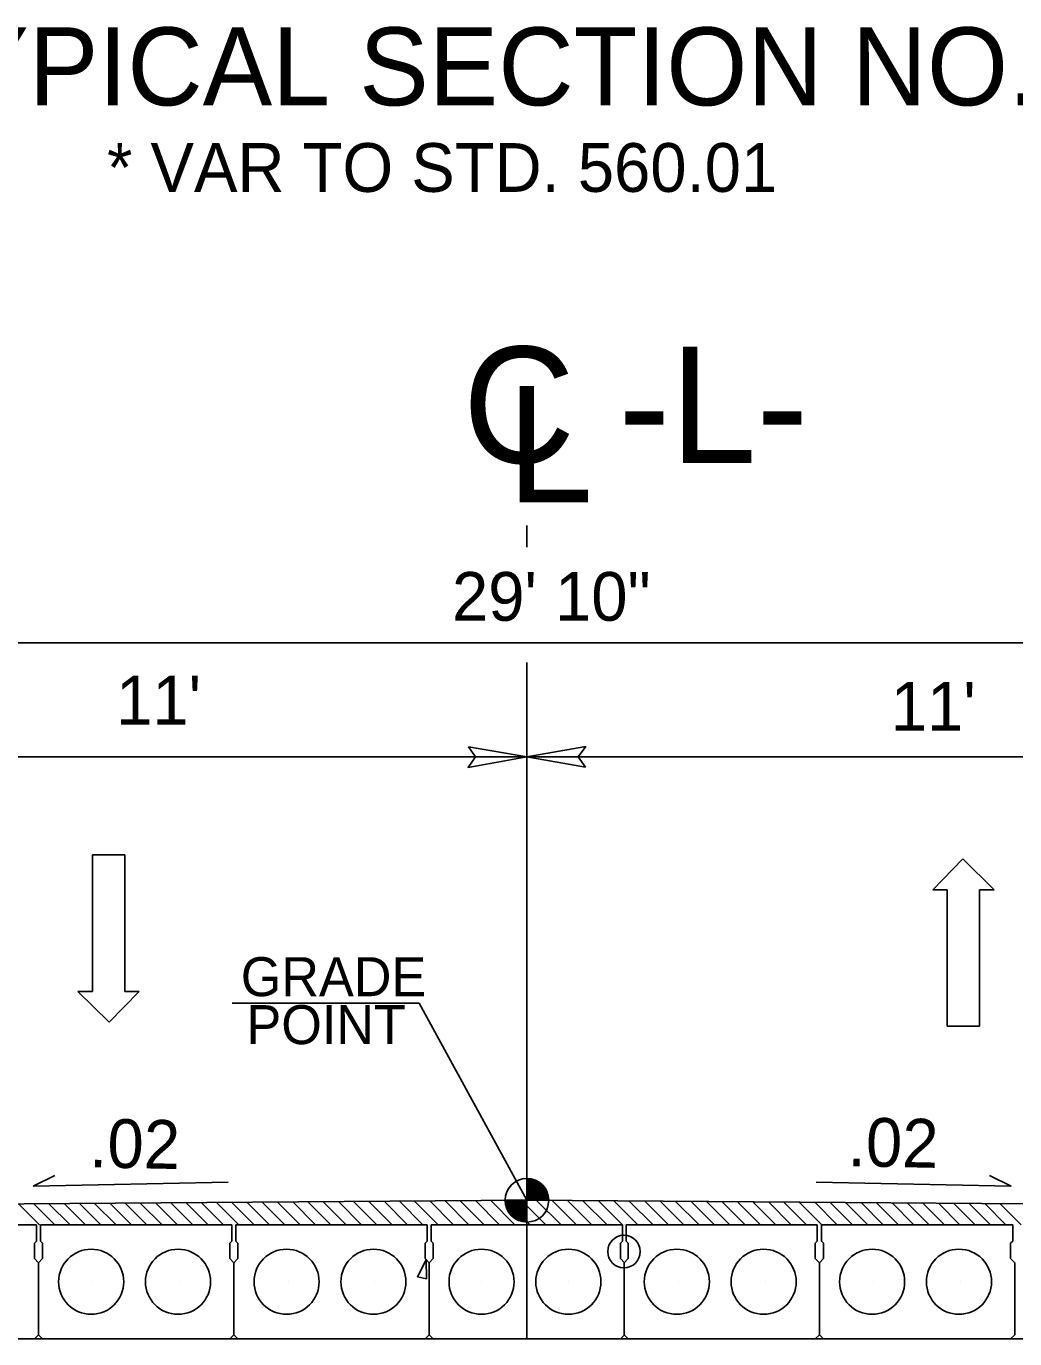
# Model space of a CAD drawing. Extents: x 575722 to 576066, y -53107 to -52774.
# Drawn here: x 575897.08 to 575912.29, y -52878.83 to -52858.63 of the extents above; entities that cross this region are included whole.
import ezdxf

# ---------------------------------------------------------------- set-up
doc = ezdxf.new("R2010")
doc.units = 0
for name, color, linetype in [('Default', 7, 'Continuous'), ('Old_Level_1', 7, 'Continuous'), ('Old_Level_11', 7, 'Continuous'), ('Old_Level_2', 7, 'Continuous'), ('Old_Level_3', 7, 'Continuous'), ('Prop Dimension Text', 7, 'Continuous'), ('Prop DSN Text', 7, 'Continuous'), ('Prop Lane Arrow CELL', 7, 'Continuous'), ('Typical Grade Point Symbol CELL', 7, 'Continuous'), ('Typical Pavement Slope CELL', 7, 'Continuous')]:
    doc.layers.add(name, color=color, linetype=linetype)

msp = doc.modelspace()

# ---------------------------------------------------------------- linework, layer by layer
at = {"layer": 'Default'}
for p, q in [((575900.113, -52877.076), (575899.772, -52876.735)), ((575900.349, -52877.076), (575900.006, -52876.734)), ((575900.585, -52877.076), (575900.241, -52876.732)), ((575900.821, -52877.076), (575900.475, -52876.73)), ((575901.057, -52877.076), (575900.71, -52876.729)), ((575901.294, -52877.076), (575900.944, -52876.727)), ((575901.53, -52877.076), (575901.179, -52876.725)), ((575901.766, -52877.076), (575901.413, -52876.724)), ((575902.002, -52877.076), (575901.647, -52876.722)), ((575902.238, -52877.076), (575901.882, -52876.72)), ((575902.474, -52877.076), (575902.116, -52876.719)), ((575902.71, -52877.076), (575902.351, -52876.717)), ((575902.946, -52877.076), (575902.585, -52876.715)), ((575903.183, -52877.076), (575902.82, -52876.714)), ((575903.419, -52877.076), (575903.054, -52876.712)), ((575903.655, -52877.076), (575903.289, -52876.71)), ((575903.891, -52877.076), (575903.523, -52876.709)), ((575904.127, -52877.076), (575903.757, -52876.707)), ((575904.363, -52877.076), (575903.992, -52876.705)), ((575904.599, -52877.076), (575904.226, -52876.703)), ((575904.835, -52877.076), (575904.461, -52876.702)), ((575905.072, -52877.076), (575904.695, -52876.7)), ((575905.308, -52877.076), (575904.932, -52876.701)), ((575905.544, -52877.076), (575905.17, -52876.702)), ((575905.78, -52877.076), (575905.407, -52876.704)), ((575906.016, -52877.076), (575905.645, -52876.706)), ((575906.252, -52877.076), (575905.883, -52876.707)), ((575906.488, -52877.076), (575906.121, -52876.709)), ((575906.724, -52877.076), (575906.359, -52876.711)), ((575906.96, -52877.076), (575906.597, -52876.713)), ((575907.197, -52877.076), (575906.834, -52876.714)), ((575907.433, -52877.076), (575907.072, -52876.716)), ((575907.669, -52877.076), (575907.31, -52876.718)), ((575907.905, -52877.076), (575907.548, -52876.719)), ((575908.141, -52877.076), (575907.786, -52876.721)), ((575908.377, -52877.076), (575908.024, -52876.723)), ((575908.613, -52877.076), (575908.261, -52876.724)), ((575908.849, -52877.076), (575908.499, -52876.726)), ((575909.086, -52877.076), (575908.737, -52876.728)), ((575909.322, -52877.076), (575908.975, -52876.73)), ((575909.558, -52877.076), (575909.213, -52876.731)), ((575909.794, -52877.076), (575909.451, -52876.733)), ((575910.03, -52877.076), (575909.688, -52876.735)), ((575910.266, -52877.076), (575909.926, -52876.736)), ((575897.28, -52877.076), (575896.959, -52876.755)), ((575897.516, -52877.076), (575897.193, -52876.754)), ((575897.752, -52877.076), (575897.427, -52876.752)), ((575897.988, -52877.076), (575897.662, -52876.75)), ((575898.224, -52877.076), (575897.896, -52876.749)), ((575898.46, -52877.076), (575898.131, -52876.747)), ((575898.696, -52877.076), (575898.365, -52876.745)), ((575898.932, -52877.076), (575898.6, -52876.744)), ((575899.169, -52877.076), (575898.834, -52876.742)), ((575899.405, -52877.076), (575899.069, -52876.74)), ((575899.641, -52877.076), (575899.303, -52876.739)), ((575899.877, -52877.076), (575899.537, -52876.737)), ((575910.502, -52877.076), (575910.164, -52876.738)), ((575910.738, -52877.076), (575910.402, -52876.74)), ((575910.975, -52877.076), (575910.64, -52876.742)), ((575911.211, -52877.076), (575910.878, -52876.743)), ((575911.447, -52877.076), (575911.115, -52876.745)), ((575911.683, -52877.076), (575911.353, -52876.747)), ((575911.919, -52877.076), (575911.591, -52876.748)), ((575912.155, -52877.076), (575911.829, -52876.75)), ((575912.391, -52877.076), (575912.067, -52876.752)), ((575894.292, -52877.076), (575897.236, -52877.076)), ((575897.236, -52877.076), (575897.236, -52877.327)), ((575897.268, -52877.076), (575897.268, -52877.076)), ((575897.298, -52877.327), (575897.298, -52877.076)), ((575897.298, -52877.076), (575900.242, -52877.076)), ((575900.242, -52877.076), (575900.242, -52877.327)), ((575900.273, -52877.076), (575900.273, -52877.076)), ((575900.303, -52877.327), (575900.303, -52877.076)), ((575900.303, -52877.076), (575903.247, -52877.076)), ((575903.247, -52877.076), (575903.247, -52877.327)), ((575903.278, -52877.076), (575903.278, -52877.076)), ((575903.308, -52877.327), (575903.308, -52877.076)), ((575903.308, -52877.076), (575906.252, -52877.076)), ((575906.252, -52877.076), (575906.252, -52877.327)), ((575906.278, -52877.076), (575906.278, -52877.076)), ((575906.283, -52877.076), (575906.283, -52877.076)), ((575906.308, -52877.327), (575906.308, -52877.076)), ((575906.308, -52877.076), (575909.252, -52877.076)), ((575909.252, -52877.076), (575909.252, -52877.327)), ((575909.283, -52877.076), (575909.283, -52877.076)), ((575909.285, -52877.076), (575909.285, -52877.076)), ((575909.315, -52877.327), (575909.315, -52877.076)), ((575909.315, -52877.076), (575912.259, -52877.076)), ((575912.259, -52877.076), (575912.259, -52877.327)), ((575912.29, -52877.076), (575912.29, -52877.076)), ((575897.236, -52877.327), (575897.205, -52877.358)), ((575897.298, -52877.327), (575897.329, -52877.358)), ((575900.242, -52877.327), (575900.21, -52877.358)), ((575900.303, -52877.327), (575900.334, -52877.358)), ((575903.247, -52877.327), (575903.215, -52877.358)), ((575903.308, -52877.327), (575903.34, -52877.358)), ((575906.252, -52877.327), (575906.221, -52877.358)), ((575906.308, -52877.327), (575906.339, -52877.358)), ((575909.252, -52877.327), (575909.221, -52877.358)), ((575909.315, -52877.327), (575909.346, -52877.358)), ((575912.259, -52877.327), (575912.227, -52877.358)), ((575897.205, -52877.598), (575897.205, -52877.358)), ((575897.329, -52877.358), (575897.329, -52877.598)), ((575900.21, -52877.598), (575900.21, -52877.358)), ((575900.334, -52877.358), (575900.334, -52877.598)), ((575903.215, -52877.598), (575903.215, -52877.358)), ((575903.34, -52877.358), (575903.34, -52877.598)), ((575906.221, -52877.598), (575906.221, -52877.358)), ((575906.339, -52877.358), (575906.339, -52877.598)), ((575909.221, -52877.598), (575909.221, -52877.358)), ((575909.346, -52877.358), (575909.346, -52877.598)), ((575912.227, -52877.598), (575912.227, -52877.358)), ((575897.268, -52877.661), (575897.205, -52877.598)), ((575897.266, -52877.661), (575897.329, -52877.598)), ((575897.266, -52878.768), (575897.266, -52877.661)), ((575897.268, -52878.768), (575897.268, -52877.661)), ((575900.273, -52877.661), (575900.21, -52877.598)), ((575900.271, -52877.661), (575900.334, -52877.598)), ((575900.271, -52878.768), (575900.271, -52877.661)), ((575900.273, -52878.768), (575900.273, -52877.661)), ((575903.278, -52877.661), (575903.215, -52877.598)), ((575903.277, -52877.661), (575903.34, -52877.598)), ((575903.277, -52878.768), (575903.277, -52877.661)), ((575903.278, -52878.768), (575903.278, -52877.661)), ((575906.283, -52877.661), (575906.221, -52877.598)), ((575906.277, -52877.661), (575906.339, -52877.598)), ((575906.278, -52878.768), (575906.278, -52877.661)), ((575906.282, -52878.768), (575906.282, -52877.661)), ((575909.283, -52877.661), (575909.221, -52877.598)), ((575909.283, -52877.661), (575909.346, -52877.598)), ((575909.283, -52878.768), (575909.283, -52877.661)), ((575909.285, -52878.768), (575909.285, -52877.661)), ((575912.29, -52877.661), (575912.227, -52877.598)), ((575912.29, -52878.768), (575912.29, -52877.661)), ((575898.101, -52877.953), (575898.101, -52877.953)), ((575899.438, -52877.953), (575899.438, -52877.953)), ((575901.107, -52877.953), (575901.107, -52877.953)), ((575902.443, -52877.953), (575902.443, -52877.953)), ((575904.085, -52877.953), (575904.085, -52877.953)), ((575905.421, -52877.953), (575905.421, -52877.953)), ((575907.112, -52877.953), (575907.112, -52877.953)), ((575908.448, -52877.953), (575908.448, -52877.953)), ((575910.119, -52877.953), (575910.119, -52877.953)), ((575911.455, -52877.953), (575911.455, -52877.953)), ((575921.254, -52878.83), (575888.313, -52878.83)), ((575897.205, -52878.83), (575894.324, -52878.83)), ((575897.205, -52878.83), (575894.324, -52878.83)), ((575897.268, -52878.768), (575897.205, -52878.83)), ((575897.329, -52878.83), (575897.266, -52878.768)), ((575900.21, -52878.83), (575897.329, -52878.83)), ((575900.21, -52878.83), (575897.329, -52878.83)), ((575900.273, -52878.768), (575900.21, -52878.83)), ((575900.334, -52878.83), (575900.271, -52878.768)), ((575903.215, -52878.83), (575900.334, -52878.83)), ((575903.215, -52878.83), (575900.334, -52878.83)), ((575903.278, -52878.768), (575903.215, -52878.83)), ((575903.34, -52878.83), (575903.277, -52878.768)), ((575906.221, -52878.83), (575903.34, -52878.83)), ((575906.221, -52878.83), (575903.34, -52878.83)), ((575906.283, -52878.768), (575906.221, -52878.83)), ((575906.339, -52878.83), (575906.277, -52878.768)), ((575909.221, -52878.83), (575906.339, -52878.83)), ((575909.283, -52878.768), (575909.221, -52878.83)), ((575909.346, -52878.83), (575909.283, -52878.768)), ((575912.227, -52878.83), (575909.346, -52878.83)), ((575912.29, -52878.768), (575912.227, -52878.83))]:
    msp.add_line(p, q, dxfattribs=at)
msp.add_lwpolyline([(575890.01, -52876.805), (575904.783, -52876.699), (575919.483, -52876.805)], dxfattribs=at)
msp.add_lwpolyline([(575903.231, -52877.614), (575903.238, -52877.908), (575903.099, -52877.877)], close=True, dxfattribs=at)
for centre, radius in [((575906.276, -52877.489), 0.25), ((575898.078, -52877.953), 0.501), ((575899.414, -52877.953), 0.501), ((575901.085, -52877.953), 0.501), ((575902.421, -52877.953), 0.501), ((575904.085, -52877.953), 0.501), ((575905.421, -52877.953), 0.501), ((575907.09, -52877.953), 0.501), ((575908.426, -52877.953), 0.501), ((575910.095, -52877.953), 0.501), ((575911.432, -52877.953), 0.501)]:
    msp.add_circle(centre, radius, dxfattribs=at)
at = {"layer": 'Old_Level_1'}
msp.add_line((575904.783, -52878.83), (575904.783, -52876.699), dxfattribs=at)
at = {"layer": 'Old_Level_11'}
for p, q in [((575919.483, -52868.121), (575890.01, -52868.121)), ((575909.81, -52869.878), (575893.61, -52869.878)), ((575915.883, -52869.878), (575899.683, -52869.878)), ((575900.249, -52873.667), (575903.126, -52873.667)), ((575904.783, -52876.699), (575903.126, -52873.667))]:
    msp.add_line(p, q, dxfattribs=at)
for points in [[(575903.884, -52869.723), (575904.783, -52869.878), (575903.878, -52870.038), (575903.993, -52869.878)], [(575905.683, -52870.033), (575904.783, -52869.878), (575905.688, -52869.718), (575905.573, -52869.878)]]:
    msp.add_lwpolyline(points, close=True, dxfattribs=at)
at = {"layer": 'Old_Level_2'}
for p, q in [((575904.783, -52866.65), (575904.783, -52866.318)), ((575904.783, -52878.39), (575904.783, -52868.422)), ((575904.783, -52873.316), (575904.783, -52873.111))]:
    msp.add_line(p, q, dxfattribs=at)
at = {"layer": 'Prop Lane Arrow CELL'}
for p, q in [((575898.098, -52873.485), (575898.098, -52871.385)), ((575898.098, -52871.385), (575898.593, -52871.385)), ((575898.593, -52871.385), (575898.593, -52873.485)), ((575911.027, -52871.92), (575911.492, -52871.447)), ((575911.492, -52871.447), (575911.972, -52871.92)), ((575911.252, -52871.92), (575911.027, -52871.92)), ((575911.252, -52874.02), (575911.252, -52871.92)), ((575911.972, -52871.92), (575911.747, -52871.92)), ((575911.747, -52871.92), (575911.747, -52874.02)), ((575898.353, -52873.958), (575897.873, -52873.485)), ((575897.873, -52873.485), (575898.098, -52873.485)), ((575898.818, -52873.485), (575898.353, -52873.958)), ((575898.593, -52873.485), (575898.818, -52873.485)), ((575911.747, -52874.02), (575911.252, -52874.02))]:
    msp.add_line(p, q, dxfattribs=at)
at = {"layer": 'Typical Grade Point Symbol CELL'}
for p, q in [((575904.783, -52876.699), (575904.783, -52876.364)), ((575904.448, -52876.699), (575904.783, -52876.699)), ((575905.119, -52876.699), (575904.783, -52876.699)), ((575904.783, -52877.035), (575904.783, -52876.699)), ((575904.783, -52876.699), (575904.783, -52877.035))]:
    msp.add_line(p, q, dxfattribs=at)
for points in [[(575904.786, -52876.364), (575904.786, -52876.364), (575904.786, -52876.699)], [(575904.793, -52876.364), (575904.793, -52876.699)], [(575904.8, -52876.365), (575904.8, -52876.699)], [(575904.807, -52876.365), (575904.807, -52876.699)], [(575904.813, -52876.365), (575904.813, -52876.699)], [(575904.82, -52876.366), (575904.82, -52876.699)], [(575904.827, -52876.367), (575904.827, -52876.699)], [(575904.833, -52876.368), (575904.833, -52876.699)], [(575904.84, -52876.368), (575904.84, -52876.699)], [(575904.847, -52876.37), (575904.847, -52876.699)], [(575904.854, -52876.371), (575904.854, -52876.699)], [(575904.86, -52876.373), (575904.86, -52876.699)], [(575904.867, -52876.374), (575904.867, -52876.699)], [(575904.874, -52876.376), (575904.874, -52876.699)], [(575904.88, -52876.378), (575904.88, -52876.699)], [(575904.887, -52876.38), (575904.887, -52876.699)], [(575904.894, -52876.382), (575904.894, -52876.699)], [(575904.901, -52876.385), (575904.901, -52876.699)], [(575904.907, -52876.388), (575904.907, -52876.699)], [(575904.914, -52876.391), (575904.914, -52876.699)], [(575904.921, -52876.394), (575904.921, -52876.699)], [(575904.927, -52876.397), (575904.927, -52876.699)], [(575904.934, -52876.4), (575904.934, -52876.699)], [(575904.941, -52876.403), (575904.941, -52876.699)], [(575904.948, -52876.407), (575904.948, -52876.699)], [(575904.954, -52876.411), (575904.954, -52876.699)], [(575904.961, -52876.414), (575904.961, -52876.699)], [(575904.968, -52876.419), (575904.968, -52876.699)], [(575904.974, -52876.423), (575904.974, -52876.699)], [(575904.981, -52876.429), (575904.981, -52876.699)], [(575904.988, -52876.433), (575904.988, -52876.699)], [(575904.995, -52876.438), (575904.995, -52876.699)], [(575905.001, -52876.444), (575905.001, -52876.699)], [(575905.008, -52876.45), (575905.008, -52876.699)], [(575905.015, -52876.456), (575905.015, -52876.699)], [(575905.021, -52876.463), (575905.021, -52876.699)], [(575905.028, -52876.47), (575905.028, -52876.699)], [(575905.035, -52876.477), (575905.035, -52876.699)], [(575905.042, -52876.485), (575905.042, -52876.699)], [(575905.048, -52876.494), (575905.048, -52876.699)], [(575905.055, -52876.503), (575905.055, -52876.699)], [(575905.062, -52876.512), (575905.062, -52876.699)], [(575905.068, -52876.523), (575905.068, -52876.699)], [(575905.075, -52876.534), (575905.075, -52876.699)], [(575904.449, -52876.699), (575904.449, -52876.736)], [(575904.456, -52876.699), (575904.456, -52876.776)], [(575904.463, -52876.699), (575904.463, -52876.799)], [(575904.469, -52876.699), (575904.469, -52876.82)], [(575904.476, -52876.699), (575904.476, -52876.835)], [(575904.483, -52876.699), (575904.483, -52876.849)], [(575904.49, -52876.699), (575904.49, -52876.862)], [(575904.496, -52876.699), (575904.496, -52876.874)], [(575904.503, -52876.699), (575904.503, -52876.884)], [(575904.51, -52876.699), (575904.51, -52876.894)], [(575904.516, -52876.699), (575904.516, -52876.903)], [(575904.523, -52876.699), (575904.523, -52876.911)], [(575904.53, -52876.699), (575904.53, -52876.92)], [(575904.537, -52876.699), (575904.537, -52876.927)], [(575904.543, -52876.699), (575904.543, -52876.934)], [(575904.55, -52876.699), (575904.55, -52876.941)], [(575904.557, -52876.699), (575904.557, -52876.947)], [(575904.563, -52876.699), (575904.563, -52876.953)], [(575904.57, -52876.699), (575904.57, -52876.959)], [(575904.577, -52876.699), (575904.577, -52876.964)], [(575904.584, -52876.699), (575904.584, -52876.97)], [(575904.59, -52876.699), (575904.59, -52876.974)], [(575904.597, -52876.699), (575904.597, -52876.978)], [(575904.604, -52876.699), (575904.604, -52876.983)], [(575904.61, -52876.699), (575904.61, -52876.987)], [(575904.617, -52876.699), (575904.617, -52876.991)], [(575904.624, -52876.699), (575904.624, -52876.995)], [(575904.631, -52876.699), (575904.631, -52876.999)], [(575904.637, -52876.699), (575904.637, -52877.002)], [(575904.644, -52876.699), (575904.644, -52877.005)], [(575904.651, -52876.699), (575904.651, -52877.008)], [(575904.657, -52876.699), (575904.657, -52877.011)], [(575904.664, -52876.699), (575904.664, -52877.014)], [(575904.671, -52876.699), (575904.671, -52877.016)], [(575904.678, -52876.699), (575904.678, -52877.018)], [(575904.684, -52876.699), (575904.684, -52877.02)], [(575904.691, -52876.699), (575904.691, -52877.022)], [(575904.698, -52876.699), (575904.698, -52877.024)], [(575904.704, -52876.699), (575904.704, -52877.025)], [(575904.711, -52876.699), (575904.711, -52877.027)], [(575904.718, -52876.699), (575904.718, -52877.028)], [(575904.725, -52876.699), (575904.725, -52877.03)], [(575904.731, -52876.699), (575904.731, -52877.031)], [(575904.738, -52876.699), (575904.738, -52877.032)], [(575904.745, -52876.699), (575904.745, -52877.033)], [(575904.751, -52876.699), (575904.751, -52877.034)], [(575904.758, -52876.699), (575904.758, -52877.034)], [(575904.765, -52876.699), (575904.765, -52877.034)], [(575904.772, -52876.699), (575904.772, -52877.035)], [(575904.778, -52876.699), (575904.778, -52877.035), (575904.778, -52877.035)], [(575905.082, -52876.546), (575905.082, -52876.699)], [(575905.089, -52876.56), (575905.089, -52876.699)], [(575905.095, -52876.576), (575905.095, -52876.699)], [(575905.102, -52876.594), (575905.102, -52876.699)], [(575905.109, -52876.617), (575905.109, -52876.699)], [(575905.115, -52876.652), (575905.115, -52876.699)]]:
    msp.add_lwpolyline(points, dxfattribs=at)
msp.add_circle((575904.783, -52876.699), 0.336, dxfattribs=at)
for start, end in [(359.9905, 89.9905), (179.9905, 269.9905)]:
    msp.add_arc((575904.783, -52876.699), 0.336, start, end, dxfattribs=at)
at = {"layer": 'Typical Pavement Slope CELL'}
for p, q in [((575897.186, -52876.485), (575897.519, -52876.318)), ((575912.233, -52876.484), (575911.9, -52876.317)), ((575900.186, -52876.422), (575897.186, -52876.485)), ((575909.233, -52876.422), (575912.233, -52876.484))]:
    msp.add_line(p, q, dxfattribs=at)

# ---------------------------------------------------------------- texts
at = {"layer": 'Old_Level_1'}
for p in [(575898.043, -52876.191), (575909.715, -52876.173)]:
    msp.add_text('.02', height=0.75, rotation=358.8084, dxfattribs=at).set_placement(p)
at = {"layer": 'Old_Level_11'}
for s, p in [('29\' 10"', (575903.63, -52867.782)), ("11'", (575898.462, -52869.379)), ("11'", (575910.383, -52869.472))]:
    msp.add_text(s, height=0.75, rotation=360, dxfattribs=at).set_placement(p)
at = {"layer": 'Old_Level_3'}
for s, p in [('GRADE', (575900.38, -52873.559)), ('POINT', (575900.468, -52874.297))]:
    msp.add_text(s, height=0.6, rotation=360, dxfattribs=at).set_placement(p)
at = {"layer": 'Prop Dimension Text'}
msp.add_text('TYPICAL SECTION NO. 2', height=1.2, dxfattribs=at).set_placement((575895.068, -52859.851))
at = {"layer": 'Prop DSN Text'}
for s, height, p in [('* VAR TO STD. 560.01', 0.75, (575898.322, -52861.182)), ('C -L-', 1.7897, (575903.796, -52865.354)), ('L', 1.79, (575904.473, -52865.961))]:
    msp.add_text(s, height=height, dxfattribs=at).set_placement(p)

doc.saveas('drawing.dxf')
